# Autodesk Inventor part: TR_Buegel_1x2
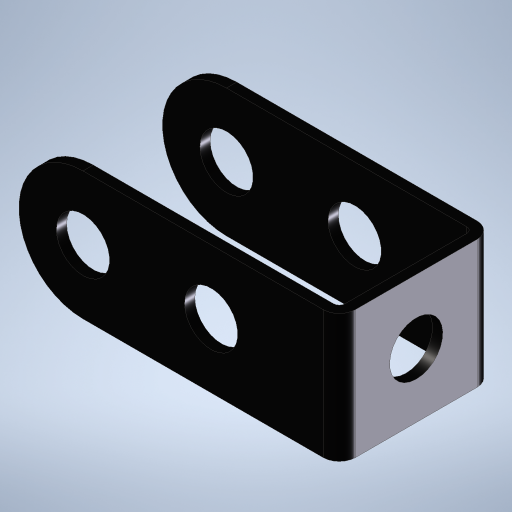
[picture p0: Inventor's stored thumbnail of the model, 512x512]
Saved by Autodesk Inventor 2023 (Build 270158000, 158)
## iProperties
Created: 2023-11
Part Number: TR_Buegel_1x2
Material: Edelstahl
Document SubType Name: Modeling
Designer: Admin
Density: 8 g/cm^3
Appearance: Halbpoliert
Author: Admin
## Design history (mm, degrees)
sketch "Skizze1"
  geometry: L1 (25, 6)-(1.25, 6); L2 (0, 4.75)-(0, -4.75); L3 (1.25, -6)-(25, -6); L4 (25, -6)-(25, -5.2); L5 (25, -5.2)-(1.25, -5.2); L6 (0.8, -4.75)-(0.8, 4.75); L7 (1.25, 5.2)-(25, 5.2); L8 (25, 5.2)-(25, 6); A1 r 1.25 centre (1.25, 4.75) between (1.25, 6) and (0, 4.75); A2 r 1.25 centre (1.25, -4.75) between (0, -4.75) and (1.25, -6); A3 r 0.45 centre (1.25, 4.75) between (1.25, 5.2) and (0.8, 4.75); A4 r 0.45 centre (1.25, -4.75) between (0.8, -4.75) and (1.25, -5.2); 5 further points
  constraints: 16 end point, 8 point on circle, 8 tangent, 4 centre point, 4 point on line, 3 horizontal, 3 perpendicular, 2 equal radius, 2 midpoint, 2 vertical alignment, 1 coincident, 1 collinear, 1 horizontal alignment, 1 parallel, 1 vertical
  dimensions: "d0" = 0.8 distance of L7.end L1.start (= Dicke); "d1" = 25 horizontal distance of point (0, 0) L1.start (computed from Einheitsmaß, HochLoch); "d2" = 0.8 horizontal distance of point (0, 0) point (0.8, 5.2) (= Dicke); "d6" = 1.25 radius of A1; "d7" = 12 distance of L3.end L1.start
extrude "Extrusion1" new body sketch "Skizze1" stored distance "d8" = 10 (= Einheitsmaß); taper "d9" = 0 deg
fillet "Rundung1" dims "d10" = 5 (= 0.5 x Einheitsmaß)
sketch "Skizze2"
  geometry: C1 r 2.075 at (-20, 0); A1 r 5 centre (-20, 0) between (-20, 5) and (-20, -5) reference; 1 further point
  constraints: 1 centre point, 1 coincident
  dimensions: "d11" = 4.15 diameter of C1 (= 2 x Radius)
extrude "Extrusion2" cut sketch "Skizze2" extent not by distance; stored distance "d12" = 0; taper "d13" = 0 deg
pattern_linear "Rechteckige Anordnung1" dims "d19" = 10 (= Einheitsmaß)
sketch "Skizze3"
  geometry: C1 r 2.075 at (0, 0); 1 further point
  constraints: 1 centre point, 1 coincident
  dimensions: "d14" = 4.15 diameter of C1 (= 2 x Radius)
extrude "Extrusion3" cut sketch "Skizze3" extent not by distance; stored distance "d15" = 0; taper "d16" = 0 deg
node "Volumenkörper1"
other parameters: "Einheitsmaß" = 10 [user parameter; used in 4 equation terms], "Radius" = 2.075 [user parameter; used in 2 equation terms], "Fasen" = 0.5 [user parameter], "Dicke" = 0.8 [user parameter; used in 2 equation terms]
